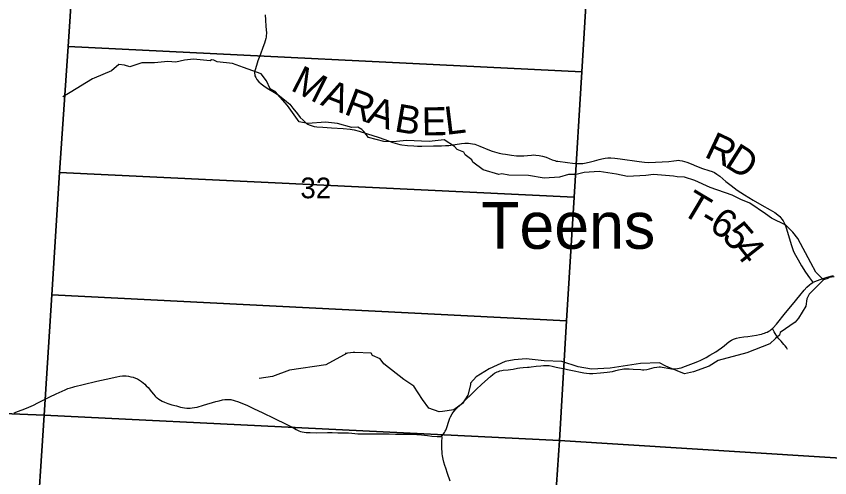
# Model space of a CAD drawing. Extents: x 396.2 to 468.4, y 232.6 to 279.1.
# Drawn here: x 421.493 to 423.138, y 271.11 to 272.044 of the extents above; entities that cross this region are included whole.
import ezdxf

# ---------------------------------------------------------------- set-up
doc = ezdxf.new("R2010")
doc.units = 0
for name, color, linetype in [('GM_X_County_Road', 7, 'Continuous'), ('GM_X_Minor_River', 7, 'Continuous'), ('GM_X_Minor_River_Text', 7, 'Continuous'), ('GM_X_Section', 7, 'Continuous'), ('GM_X_Section_Text', 7, 'Continuous'), ('GM_X_Township_Road', 7, 'Continuous'), ('GM_X_Township_Road_Text', 7, 'Continuous')]:
    doc.layers.add(name, color=color, linetype=linetype)

msp = doc.modelspace()

# ---------------------------------------------------------------- linework, layer by layer
at = {"layer": 'GM_X_County_Road'}
for points in [[(421.4889, 271.2417), (421.4982, 271.245), (421.5109, 271.2501), (421.5191, 271.2534), (421.528, 271.2575), (421.5373, 271.262), (421.5495, 271.2682), (421.5615, 271.2742), (421.5742, 271.2803), (421.5922, 271.2885), (421.5978, 271.2907), (421.6028, 271.2925), (421.6075, 271.2939), (421.6121, 271.295), (421.6285, 271.2988), (421.6564, 271.3055), (421.6754, 271.3099), (421.697, 271.3146), (421.7027, 271.3156), (421.708, 271.3162), (421.7119, 271.3163), (421.7157, 271.3162), (421.7205, 271.3156), (421.7252, 271.3148), (421.7298, 271.3136), (421.7342, 271.312), (421.7383, 271.3102), (421.7425, 271.3078), (421.7465, 271.3051), (421.7503, 271.3022), (421.7536, 271.2994), (421.7564, 271.2965), (421.7598, 271.2928), (421.7667, 271.2844), (421.771, 271.2792), (421.7744, 271.2755), (421.7762, 271.2737), (421.7784, 271.2719), (421.7817, 271.2694), (421.7851, 271.2673), (421.7886, 271.2654), (421.793, 271.2635), (421.8001, 271.2608), (421.8082, 271.2581), (421.8172, 271.2555), (421.8255, 271.2534), (421.8334, 271.2519), (421.8383, 271.2514), (421.8416, 271.2512), (421.845, 271.2512), (421.8493, 271.2515), (421.8541, 271.2522), (421.8595, 271.2534), (421.872, 271.257), (421.8969, 271.2644), (421.9035, 271.2662), (421.9104, 271.2678), (421.9154, 271.2685), (421.9204, 271.2688), (421.9228, 271.2688), (421.925, 271.2687), (421.9273, 271.2685), (421.9295, 271.2681), (421.9322, 271.2673), (421.9362, 271.266), (421.9409, 271.2643), (421.9495, 271.2611), (421.9612, 271.2562), (421.9747, 271.25), (421.9903, 271.2425), (422.0159, 271.2301), (422.0393, 271.2189), (422.0433, 271.2169), (422.0471, 271.2149), (422.0503, 271.2132), (422.0591, 271.2081), (422.062, 271.2065), (422.065, 271.2052), (422.0683, 271.2041), (422.0716, 271.2032), (422.0753, 271.2025), (422.0794, 271.2021), (422.0877, 271.2017), (422.1003, 271.2013), (422.1229, 271.2019), (422.1324, 271.2019), (422.1434, 271.2013), (422.1588, 271.2012), (422.165, 271.2012), (422.1717, 271.2008), (422.1844, 271.1992), (422.1911, 271.1989), (422.1979, 271.1991), (422.2103, 271.1994), (422.2267, 271.1992), (422.2398, 271.1993), (422.2472, 271.1992), (422.2605, 271.1988), (422.2707, 271.1987), (422.2843, 271.1986), (422.2939, 271.1982), (422.3036, 271.1977), (422.3129, 271.1971), (422.3247, 271.196), (422.3339, 271.1948), (422.3442, 271.1937), (422.3483, 271.1937), (422.3515, 271.1941), (422.3533, 271.195), (422.3557, 271.1973), (422.3579, 271.1998), (422.3595, 271.2021), (422.3608, 271.2043), (422.3618, 271.2068), (422.3631, 271.21), (422.3688, 271.2266), (422.3703, 271.2309), (422.3717, 271.2339), (422.3746, 271.2395), (422.3762, 271.242), (422.3781, 271.2444), (422.3825, 271.2493), (422.392, 271.2587), (422.4232, 271.2886), (422.4349, 271.2996), (422.452, 271.3155), (422.4568, 271.3194), (422.4605, 271.3219), (422.4632, 271.3234), (422.4656, 271.3245), (422.4685, 271.3256), (422.4713, 271.3265), (422.4749, 271.3272), (422.478, 271.3277), (422.4881, 271.3287), (422.4928, 271.3293), (422.4979, 271.3303), (422.5071, 271.3323), (422.5117, 271.333), (422.5182, 271.3336), (422.5268, 271.3338), (422.5303, 271.3341), (422.5347, 271.3346), (422.5447, 271.3358), (422.5541, 271.337), (422.5597, 271.3375), (422.5645, 271.3377), (422.5677, 271.3375), (422.5712, 271.3372), (422.5773, 271.3361), (422.5851, 271.3343), (422.6023, 271.3305), (422.6082, 271.3292), (422.6149, 271.3278), (422.6214, 271.3264), (422.6341, 271.3237), (422.641, 271.3225), (422.6467, 271.3217), (422.6522, 271.3214), (422.659, 271.3214), (422.6745, 271.3225), (422.6884, 271.3238), (422.6993, 271.3256), (422.7059, 271.3271), (422.7111, 271.3285), (422.7185, 271.3301), (422.7217, 271.3306), (422.7257, 271.3309), (422.7288, 271.331), (422.7326, 271.3309), (422.7411, 271.3303), (422.7561, 271.329), (422.7597, 271.3289), (422.7626, 271.3289), (422.7683, 271.3295), (422.774, 271.3308), (422.7832, 271.3331), (422.7884, 271.3341), (422.7931, 271.3345), (422.7961, 271.3344), (422.7992, 271.3341), (422.8148, 271.3312), (422.8186, 271.3306), (422.8223, 271.3305), (422.8265, 271.3308), (422.8305, 271.3312), (422.8338, 271.3318), (422.8375, 271.3328), (422.8465, 271.3358), (422.8628, 271.3419), (422.8718, 271.3456), (422.8775, 271.348), (422.8816, 271.3502), (422.8881, 271.3539), (422.8956, 271.3583), (422.9076, 271.3654), (422.9128, 271.3686), (422.9193, 271.3732), (422.9248, 271.3775), (422.9303, 271.382), (422.9341, 271.385), (422.9393, 271.3884), (422.9436, 271.3908), (422.9494, 271.393), (422.9559, 271.3942), (422.9644, 271.3953), (422.9726, 271.3964), (422.9902, 271.399), (422.9963, 271.4002), (423.0002, 271.401), (423.0036, 271.402), (423.0065, 271.4029), (423.0093, 271.4039), (423.0117, 271.405), (423.015, 271.4067), (423.0175, 271.4084), (423.0197, 271.4101), (423.0226, 271.4126), (423.0237, 271.4138), (423.0305, 271.4213), (423.0488, 271.4438), (423.0627, 271.4608), (423.0775, 271.4789), (423.0864, 271.4901), (423.0919, 271.4959), (423.0975, 271.5008), (423.101, 271.5034), (423.1039, 271.5053)], [(423.1039, 271.5053), (423.1045, 271.5057), (423.107, 271.5069), (423.1112, 271.5087), (423.1211, 271.5123), (423.1333, 271.5162), (423.1458, 271.5195)], [(422.3707, 271.1036), (422.3654, 271.1188), (422.3618, 271.1295), (422.3601, 271.1348), (422.3582, 271.1417), (422.3566, 271.1482), (422.3554, 271.1544), (422.3548, 271.1585), (422.3544, 271.1633), (422.3542, 271.1679), (422.3541, 271.1727), (422.3542, 271.1835), (422.3543, 271.1917), (422.3533, 271.195)]]:
    msp.add_lwpolyline(points, dxfattribs=at)
at = {"layer": 'GM_X_Minor_River'}
for points in [[(422.0069, 271.8973), (421.9997, 271.9132), (421.9887, 271.9277), (421.9528, 271.9401), (421.9309, 271.9481), (421.8999, 271.9518), (421.893, 271.9552), (421.8885, 271.9559), (421.8855, 271.954), (421.8518, 271.9574), (421.8337, 271.9551), (421.8159, 271.9508), (421.7997, 271.9523), (421.7728, 271.9496), (421.7471, 271.9495), (421.7229, 271.9415), (421.7124, 271.9449), (421.7006, 271.9464), (421.6859, 271.9334), (421.6508, 271.9185), (421.6477, 271.9174), (421.6024, 271.8895), (421.5877, 271.8811)], [(423.147, 271.5168), (423.1368, 271.5152), (423.1342, 271.5133), (423.1259, 271.511), (423.11, 271.5262), (423.0998, 271.5448), (423.0736, 271.5945), (423.0638, 271.6074), (423.0494, 271.6214), (423.0203, 271.6354), (423.0085, 271.6442), (422.9764, 271.6658), (422.9582, 271.6729), (422.9412, 271.682), (422.8966, 271.6975), (422.8656, 271.7115), (422.8444, 271.7183), (422.8297, 271.7194), (422.8221, 271.7201), (422.782, 271.7235), (422.7665, 271.7215), (422.7291, 271.7199), (422.7068, 271.7248), (422.672, 271.73), (422.6414, 271.7277), (422.6255, 271.7235), (422.6097, 271.7238), (422.5915, 271.7181), (422.5609, 271.7161), (422.5291, 271.7217), (422.4894, 271.7224), (422.4754, 271.7254), (422.4694, 271.7235), (422.4376, 271.7333), (422.4165, 271.7485), (422.4146, 271.7534), (422.4013, 271.7633), (422.3987, 271.7693), (422.3847, 271.7746), (422.3794, 271.7807), (422.3589, 271.7936), (422.3283, 271.7908), (422.2826, 271.7926), (422.2554, 271.7899), (422.2365, 271.7906), (422.2058, 271.7985), (422.1964, 271.8111), (422.1922, 271.8149), (422.1843, 271.8194), (422.1718, 271.819), (422.1431, 271.8269), (422.1185, 271.8299), (422.083, 271.8271), (422.0652, 271.8301), (422.0417, 271.8632), (422.0171, 271.8916), (422.0069, 271.8973)], [(423.1259, 271.511), (423.0964, 271.482), (423.0919, 271.4721), (423.09, 271.4573), (423.0749, 271.4333), (423.0685, 271.425), (423.0383, 271.4044), (423.0364, 271.3986), (423.0288, 271.3922), (423.0171, 271.3815), (422.9707, 271.3631), (422.9128, 271.3474), (422.8943, 271.336), (422.8626, 271.3245), (422.8448, 271.3206), (422.8115, 271.3343), (422.807, 271.3361), (422.7938, 271.3426), (422.7556, 271.3417), (422.694, 271.3317), (422.6566, 271.3301), (422.6297, 271.335), (422.5964, 271.3452), (422.5609, 271.347), (422.5242, 271.3511), (422.5004, 271.3491), (422.4823, 271.3457), (422.4498, 271.3308), (422.423, 271.3147), (422.412, 271.3018), (422.4116, 271.298), (422.4067, 271.2774), (422.3954, 271.2607), (422.3784, 271.2477), (422.3554, 271.2442), (422.3486, 271.2435), (422.3274, 271.251), (422.3149, 271.2689), (422.2975, 271.2958), (422.2771, 271.3091), (422.2369, 271.3409), (422.229, 271.3508), (422.2135, 271.3576), (422.2108, 271.3621), (422.178, 271.3636), (422.1746, 271.3636), (422.1587, 271.362)], [(422.1627, 271.3624), (422.1197, 271.3386), (422.046, 271.3277), (422.0113, 271.3155), (421.9843, 271.311)]]:
    msp.add_lwpolyline(points, dxfattribs=at)
at = {"layer": 'GM_X_Section'}
for points in [[(420.5671, 272.2854), (421.6151, 272.2373), (421.5983, 271.983), (421.5809, 271.7277), (421.5654, 271.4805), (421.55, 271.2368), (420.4987, 271.28)], [(421.6153, 272.2403), (422.6516, 272.1773), (422.6367, 271.9315), (421.5983, 271.983), (421.6151, 272.2373)], [(422.6516, 272.1773), (422.7982, 272.1692), (423.6892, 272.117), (423.6926, 272.1168), (423.6781, 271.864), (423.6567, 271.5072), (423.6324, 271.1204), (422.5921, 271.1859), (422.6061, 271.4281), (422.6216, 271.6781), (422.6367, 271.9315)], [(422.6367, 271.9315), (422.6216, 271.6781), (421.5809, 271.7277), (421.5983, 271.983)], [(421.5809, 271.7277), (422.6216, 271.6781), (422.6061, 271.4281), (421.5654, 271.4805)], [(422.6061, 271.4281), (422.5921, 271.1859), (421.55, 271.2368), (421.5654, 271.4805)], [(420.4987, 271.28), (421.55, 271.2368), (421.5332, 270.9795), (421.5171, 270.7352), (421.5012, 270.4826), (421.4857, 270.2238), (420.43, 270.2709)], [(422.5921, 271.1859), (422.5738, 270.9188), (421.5332, 270.9795), (421.55, 271.2368)], [(423.6324, 271.1204), (423.6151, 270.8701), (422.5738, 270.9188), (422.5921, 271.1859)]]:
    msp.add_lwpolyline(points, close=True, dxfattribs=at)
at = {"layer": 'GM_X_Township_Road'}
for points in [[(421.9969, 272.0467), (421.9976, 272.0366), (421.9983, 272.0232), (421.9991, 272.0101), (421.9987, 272.0033), (421.9986, 272.0014), (421.9982, 271.9992), (421.9969, 271.9944), (421.9955, 271.9898), (421.9923, 271.9804), (421.987, 271.9671), (421.9843, 271.9604), (421.9822, 271.954), (421.9793, 271.9445), (421.9762, 271.9352), (421.9754, 271.9316), (421.9752, 271.9286), (421.9755, 271.9257), (421.9761, 271.9234), (421.9775, 271.9203), (421.9799, 271.9162), (421.9839, 271.9114), (421.9884, 271.9071), (421.9937, 271.9029), (422.0009, 271.8982), (422.0155, 271.8898), (422.0228, 271.885), (422.0327, 271.8776), (422.04, 271.8718), (422.0464, 271.8658), (422.0529, 271.8581), (422.062, 271.8462), (422.0675, 271.8393), (422.0732, 271.8335), (422.0782, 271.8292), (422.0806, 271.8274), (422.0832, 271.8258), (422.0854, 271.8245), (422.088, 271.8233), (422.0914, 271.8221), (422.0956, 271.8211), (422.1014, 271.8204), (422.1133, 271.8193), (422.131, 271.8182), (422.1546, 271.8167), (422.1689, 271.8153), (422.1768, 271.8139), (422.1865, 271.8115), (422.2039, 271.8059), (422.225, 271.799), (422.2388, 271.7945), (422.2549, 271.7888), (422.2644, 271.7857), (422.2692, 271.7845), (422.2733, 271.7839), (422.2844, 271.7826), (422.2971, 271.7817), (422.3045, 271.7814), (422.3134, 271.7813), (422.3373, 271.7817), (422.3532, 271.782), (422.3612, 271.7823), (422.3682, 271.7828), (422.3935, 271.7866), (422.4006, 271.7873), (422.4046, 271.7873), (422.4081, 271.7871), (422.412, 271.7867), (422.4157, 271.7861), (422.4203, 271.7849), (422.431, 271.7811), (422.4501, 271.773), (422.4554, 271.7711), (422.4604, 271.7695), (422.47, 271.767), (422.4767, 271.7656), (422.4828, 271.7646), (422.4946, 271.763), (422.5046, 271.7618), (422.5116, 271.7614), (422.5158, 271.7613), (422.5196, 271.7615), (422.527, 271.7623), (422.5351, 271.7631), (422.5398, 271.7633), (422.5438, 271.7631), (422.5507, 271.7624), (422.5574, 271.761), (422.5646, 271.7587), (422.5769, 271.7537), (422.5825, 271.7519), (422.5853, 271.7511), (422.5884, 271.7505), (422.6078, 271.7478), (422.6182, 271.7464), (422.6268, 271.7459), (422.6335, 271.7459), (422.6387, 271.7463), (422.6425, 271.7469), (422.6516, 271.7486), (422.6624, 271.7515), (422.672, 271.7542), (422.6774, 271.7557), (422.6809, 271.7565), (422.6843, 271.757), (422.6895, 271.7574), (422.6958, 271.7574), (422.7036, 271.7566), (422.7147, 271.7555), (422.7529, 271.7501), (422.764, 271.7489), (422.7717, 271.7484), (422.7856, 271.7489), (422.7997, 271.7495), (422.8128, 271.7503), (422.8228, 271.7516), (422.8287, 271.7523), (422.8319, 271.7525), (422.8348, 271.7523), (422.84, 271.7514), (422.8448, 271.7502), (422.8493, 271.7487), (422.858, 271.7453), (422.869, 271.7406), (422.8808, 271.7362), (422.8941, 271.7322), (422.9006, 271.7298), (422.9051, 271.7277), (422.9099, 271.7247), (422.9158, 271.7201), (422.9279, 271.7095), (422.9386, 271.7015), (422.9513, 271.6919), (422.9662, 271.6828), (422.9836, 271.672), (423.0007, 271.6619), (423.018, 271.6524), (423.0269, 271.6468), (423.033, 271.6423), (423.0372, 271.6386), (423.0417, 271.6333), (423.0442, 271.6301), (423.0477, 271.6234), (423.0508, 271.6142), (423.0605, 271.5821), (423.0623, 271.5761), (423.0644, 271.57), (423.0665, 271.5652), (423.0691, 271.5604), (423.0743, 271.5509), (423.081, 271.5391), (423.089, 271.5265), (423.0971, 271.5148), (423.1031, 271.5064), (423.1039, 271.5053)], [(423.0531, 271.3698), (423.0506, 271.3737), (423.048, 271.3773), (423.0457, 271.3801), (423.0429, 271.3833), (423.0401, 271.3864), (423.0356, 271.3916), (423.0314, 271.397), (423.028, 271.4021), (423.0262, 271.4052), (423.0233, 271.411), (423.0226, 271.4126)]]:
    msp.add_lwpolyline(points, dxfattribs=at)

# ---------------------------------------------------------------- texts
at = {"layer": 'GM_X_Minor_River_Text'}
msp.add_text('Teens', height=0.0947, rotation=359.9977, dxfattribs=at).set_placement((422.4335, 271.5735))
at = {"layer": 'GM_X_Section_Text'}
msp.add_text('32', height=0.04186, rotation=0, dxfattribs=at).set_placement((422.0679, 271.6757))
at = {"layer": 'GM_X_Township_Road_Text'}
for s, rotation, p in [('M', 333.3729, (422.0461, 271.8953)), ('A', 338.7437, (422.1066, 271.8653)), ('R', 339.4844, (422.1539, 271.8468)), ('A', 341.4264, (422.1996, 271.8298)), ('B', 350.1678, (422.2562, 271.8115)), ('E', 0.9004, (422.3137, 271.8027)), ('L', 6.9711, (422.3628, 271.8038)), ('R', 334.7983, (422.8825, 271.7604)), ('D', 327.6008, (422.9231, 271.7415)), ('T', 329.1935, (422.8353, 271.6459)), ('6', 329.1697, (422.8919, 271.6122)), ('-', 329.1895, (422.8718, 271.6241)), ('5', 310.971, (422.9183, 271.5973)), ('4', 308.1819, (422.9408, 271.5714))]:
    msp.add_text(s, height=0.0568, rotation=rotation, dxfattribs=at).set_placement(p)

doc.saveas('drawing.dxf')
